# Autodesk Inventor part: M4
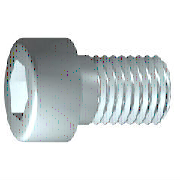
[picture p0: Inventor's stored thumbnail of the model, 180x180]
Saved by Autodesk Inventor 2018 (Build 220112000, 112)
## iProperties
IsCustomPart: 0
Created: 2016-04
Part Number: M4
Material: 강철, 연강
Description: 6각머리 태핑 나사
Document SubType Name: Modeling
Standard: KS B 1003
Designer: mdu
Standards Organization: KS
Language: ko-KR
Size Designation: M 4 x 10
Categories: <MemberInstance><Categories><Category DisplayName="조임쇠" InternalName="e4da775c-781d-43d5-af7c-5136215cf5a6" Mnemonic="FSTN"><Category DisplayName="볼트" InternalN
Density: 7.86 g/cm^3
Mass: 2.0371 g
Surface Area: 3.0572 cm^2
Volume: 0.259174 cm^3
Appearance: 강철
Author: mdu
Revision Number: 1
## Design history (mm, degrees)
sketch "스케치1"
  geometry: L1 (-1, 0)-(10, 0); L2 (10, 0)-(10, 2); L3 (10, 2)-(1.75, 2); L4 (1.75, 2)-(1.32, 2); L5 (1.32, 2)-(0, 2); L6 (0, 2)-(0, 3.5); L7 (0, 3.5)-(-4, 3.5); L8 (-4, 3.5)-(-4, 1.732); L9 (-4, 1.732)-(-2, 1.732); L10 (-2, 1.732)-(-1, 0); L11 (-6.8, 0)-(12.8, 0) reference; L12 (0, -0.7)-(0, 4.2) reference; L13 (1.75, 2)-(0, 2)
  constraints: 22 end point, 6 parallel, 2 collinear, 2 perpendicular, 1 horizontal, 1 point on line
  dimensions: "d1" = 8.25 distance from line of L3.end L2 (= GEL); "d2" = 0.42952 distance of L4.end L3.end (computed from GAL); "d3" = 4 distance between parallel lines of L8 L6 (= KOH); "d4" = 2 distance of L8.end L9.end (= INTI); "d5" = 60 deg angle of L10 L1; "d6" = 4 diameter of L3 L1 (= GD); "d7" = 4 diameter of L5 L1 (= BDM); "d8" = 3.4641 diameter of L9 L1 (= 1.1547 x SW); "d9" = 7 diameter of L7 L1 (= KOD); "d26" = 10 distance between parallel lines of L12 L2 (= NLG)
revolve "본체" sketch "스케치1" stored, may be unused: angle "d10" = 90 deg
sketch "스케치2"
  geometry: L1 (0, -4.9)-(0, 4.9) reference; L2 (-4.9, 0)-(4.9, 0) reference; L3 (1.732, 0)-(0.866, -1.5); L4 (0.866, -1.5)-(-0.866, -1.5); L5 (-0.866, -1.5)-(-1.732, 0); L6 (-1.732, 0)-(-0.866, 1.5); L7 (-0.866, 1.5)-(0.866, 1.5); L8 (0.866, 1.5)-(1.732, 0); 2 further points
  constraints: 12 end point, 1 coincident, 1 horizontal alignment, 1 point on line, 12 other
extrude "슬롯" join sketch "스케치2" stored distance "d11" = 10; taper "d12" = 0 deg
workplane "Work Plane1"
fillet "Fillet2" dims "d30" = 0.1 (= R)
body "Solid1"
fillet "모깎기1" dims "d17" = 0.4 (= RR)
feature "스레드" dims "d13" = 8.25 (= GEL), "d14" = 0
chamfer "모따기1" distance "d15" = 0.42941 (= -0.5 x SPD + 0.5 x GD); stored, may be unused: second distance "d16" = 0.42941 (= GUL), angle "d27" = 45 deg
other parameters: "GD" = 4 (= NND) [user parameter; used in 2 equation terms], "NLG" = 10 [user parameter; used in 1 equation term], "GEL" = 8.25 [user parameter; used in 2 equation terms], "KOD" = 7 [user parameter; used in 1 equation term], "KOH" = 4 [user parameter; used in 1 equation term], "INTI" = 2 [user parameter; used in 1 equation term], "GAL" = 0.42941 (= 0.61345 x PTC) [user parameter; used in 1 equation term], "GUL" = 0.42941 (= 0.61345 x PTC) [user parameter; used in 1 equation term], "BDM" = 4 (= NND) [user parameter; used in 1 equation term], "SW" = 3 [user parameter; used in 2 equation terms], "RR" = 0.4 [user parameter; used in 1 equation term], "SPD" = 3.14117 (= NND - 1.2269 x PTC) [user parameter; used in 1 equation term], "d19" = 0, "d28" = 0, "d29" = 0, "R" = 0.1 [user parameter; used in 1 equation term], "PHH" = 0.2 [user parameter], "GD1" = 3.14117 (= THREADDIA - 1.2269 x PTC) [user parameter], "THREADDIA" = 4 [user parameter; used in 1 equation term], "FAWI" = 45 deg [user parameter], "TPU" = 14.28571 (computed from PTC) [user parameter], "PTC" = 0.7 [user parameter; used in 5 equation terms], "NND" = 4 [user parameter; used in 3 equation terms], "TOA" = 30 deg [user parameter], "E0" = 3.465 (= 1.155 x SW) [user parameter]
